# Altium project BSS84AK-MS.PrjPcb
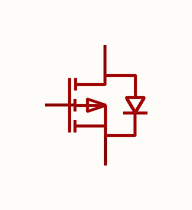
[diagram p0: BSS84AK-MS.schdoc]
1 sheet, 1 parts. Net scope: global (net labels, ports and power ports of the same name join across sheets).

## Sheet BSS84AK-MS.schdoc
size 127 x 101 mm

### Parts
Q?  bss84ak-ms  [SOT-23-3_L2.9-W1.3-P1.90-LS2.4-BR]  (value not drawn)

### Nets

Not connected (* = marked no-connect by the designer): Q? 1(G) 2(S) 3(D)

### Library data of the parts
Q? = bss84ak-ms: 数量:1个P沟道;漏源电压(Vdss):55V;连续漏极电流(Id):300mA;导通电阻(RDS(on)):4.5Ω@10V;耗散功率(Pd):1W;阈值电压(Vgs(th)):1.7V;; Manufacturer: MSKSEMI(美森科); AddInBom: yes; ModelId: c62791f0466c4ae2a892c056b845b0ca; ModelName: SOT-23-3P_L2.9-W1.3-H1.0-LS2.4-P0.95; ModelTransform: 98.425,114.173,0,180,0,0,0.0005,-0.0005,0; Number: 1个P沟道; Drain to Source Voltage: 55V; Current - Continuous Drain(Id): 300mA; Pd - Power Dissipation: 1W; Gate Threshold Voltage (Vgs(th)): 1.7V; Gate Charge(Qg): 2.8nC@10V; Input Capacitance(Ciss): 30.5pF; Reverse Transfer Capacitance (Crss@Vds): 7pF; Output Capacitance(Coss): 15.1pF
